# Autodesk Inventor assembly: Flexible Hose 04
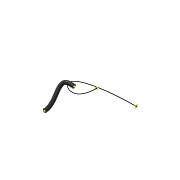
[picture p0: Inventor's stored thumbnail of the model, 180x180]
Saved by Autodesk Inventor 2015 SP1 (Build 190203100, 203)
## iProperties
Created: 2013-02
Part Number: Flexible Hose 04
Document SubType Name: Assembly
Designer: Marci
Name: Hydraulic Hose - No Fittings
ActiveState: True
PipeType: Flexible Hose
Material: UnInitValue
Standard: UnInitValue
FittingMaterial: UnInitValue
FittingStandard: UnInitValue
RouteDirection90: UnInitValue
RouteDirection45: UnInitValue
IsFlanged: UnInitValue
IsButtWelded: UnInitValue
DiameterType: Nominal
Diameter: 1/4
Schedule: ID=0.25
OD: 1,4986
ID: 0,635
Ending: UnInitValue
IntermediateSegmentsMin: UnInitValue
IntermediateSegmentsMax: UnInitValue
IntermediateSegmentsInc: UnInitValue
TerminationSegmentsMin: UnInitValue
TerminationSegmentsMax: UnInitValue
TerminationSegmentsInc: UnInitValue
RoundUpValue: 0.125 in
DefaultBendRadius: UnInitValue
BendRadius: 0.500 in
PipingComponentColor: Blue (Flat)
PipeKey: v3#d489867e-ac9b-47ea-b952-0a1b885f66be#1
CouplingKey: UnInitValue
Elbow90Key: UnInitValue
Elbow45Key: UnInitValue
SuppressStartFitting: True
SuppressEndFitting: True
FlangeKey: UnInitValue
GasketKey: UnInitValue
Gap: UnInitValue
UseSubASM: True
_ComponentInfo: <CS><C N="Pipe" R="0,749300" OR="0,749300" IR="0,317500" PL="PL" PartType="pipe" SymKey="" PN="Parker hidraulikatömlő - No Skive 1/4"><CO N="1"><FE V="0"/><FD V
ShowGap: UnInitValue
MixedUnits: UnInitValue
UseFlangsForCouplings: UnInitValue
IsSelfDraining: UnInitValue
ElbowCustomKey: UnInitValue
Angle: UnInitValue
Author: Marci
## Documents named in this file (3)
- C:\Users\TREINA11\Desktop\#01- Polymechanics and Automation\01 - 3D Models\Pneumatic System\Teljes hajtás.Hose04.iam
- C:\Users\TREINA11\Desktop\#01- Polymechanics and Automation\01 - 3D Models\Pneumatic System\Teljes hajtás.Hose04.ipt
- C:\Users\TREINA11\Desktop\#01- Polymechanics and Automation\01 - 3D Models\Pneumatic System\pifhose.1360342745393.ipt
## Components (2 placed, 2 different names)
1. Hose04
2. Flexible Hose:1
